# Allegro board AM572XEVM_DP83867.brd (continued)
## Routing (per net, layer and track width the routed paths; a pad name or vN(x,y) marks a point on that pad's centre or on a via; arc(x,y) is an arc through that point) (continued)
MMC1_SD_CD: length 58
  TOP w0.12: v1(63.87,9.26) 63.1,9.26 62.77,9.59 R272.2 62.77,10.99 62.57,11.19 D23.5 ; U11.W7 v2(73.79,44.81)
  INT_L3 w0.094: v2(73.79,44.81) 74.17,45.19 74.17,45.72 74.48,46.03 74.74,46.03 74.96,46.25 74.96,46.64 75.15,46.83 77.12,46.83 78.16,45.79 78.16,25.59 77.22,24.64 77.22,16.38 73.33,12.5 65.58,12.5 63.87,10.79 v1(63.87,9.26)
  BOTTOM w0.12: P12.9 v1(63.87,9.26)
MMC2_3V3: length 17.9
  TOP w0.203: U22.P3 94.61,47.36 94.61,47.62
  TOP w0.254: U22.E6 v2(92.83,43.04) 92.85,43.06 U22.F5 ; U22.J10 91.43,44.57 v2(91.44,44.58) 91.32,44.69 U22.K9
  TOP w0.381: v1(95.25,48.13) v1(94.61,48.13) 94.61,47.62
  BOTTOM w0.254: v2(91.44,44.58) 91.5,44.51 C266.1
  BOTTOM w0.381: R259.1 R254.1 R258.1 R253.1 R252.1 R257.1 R256.1 v1(97.28,37.88) 97.28,40.35 R255.1 ; R251.1 93.15,43.37 v2(92.83,43.04) 92.65,43.04 92.27,43.42 R250.1 ; v2(91.44,44.58) 90.77,44.58 C267.2 ; v1(95.25,48.13) 95.25,48.64 95.09,48.8 R249.1 v1(94.61,48.13) v1(95.25,48.13)
MMC2_CLK: length 33.8
  TOP w0.12: v2(92.33,45.57) U22.M6 ; U11.J7 v2(73.79,36.01)
  SIG_L10 w0.094: v2(92.33,45.57) 92.73,45.97 94.87,45.97 95,46.11 95,46.39 94.91,46.48 91.57,46.48 85.37,40.28 82.06,40.28 81.79,40.01 79.25,40.01 78.87,40.39 76.03,40.39 75.81,40.16 75.81,39.87 75.52,39.58 75.23,39.58 75.01,39.36 75.01,39.07 74.73,38.79 73.58,38.79 73.41,38.61 73.41,36.45 73.79,36.07 v2(73.79,36.01)
  BOTTOM w0.12: v2(92.33,45.57) 92.27,45.51 R250.2
MMC2_CMD: length 34
  TOP w0.12: v2(93.07,45.57) 93.33,45.82 U22.M5 ; U11.H6 v2(74.59,35.21)
  SIG_L10 w0.094: v2(93.07,45.57) 93.45,45.19 93.45,43.41 95.38,41.48 95.38,41.47 95.4,41.45 95.4,39.52 94.13,38.25 88.03,38.25 83.44,33.66 79.17,33.66 78.74,33.23 76.03,33.23 75.81,33.45 75.81,33.72 75.54,33.98 75.24,33.98 74.96,34.26 74.96,34.56 74.59,34.94 v2(74.59,35.21)
  BOTTOM w0.12: v2(93.07,45.57) 93.15,45.49 R251.2
MMC2_DAT0: length 33.8
  TOP w0.12: v1(94.74,39.5) 94.33,39.91 U22.A3 ; U11.J4 v2(76.19,36.01)
  SIG_L10 w0.094: v2(76.19,36.01) 76.19,35.96 76.56,35.58 78.84,35.58 79.58,36.32 83.69,36.32 87.27,39.9 87.91,39.9 88.15,40.15 88.15,40.68 88.23,40.77 88.35,40.77 88.43,40.68 88.43,39.98 88.52,39.9 88.63,39.9 88.72,39.98 88.72,40.68 88.8,40.77 88.92,40.77 89,40.68 89,39.98 89.08,39.9 89.2,39.9 89.28,39.98 89.28,40.68 89.36,40.77 89.48,40.77 89.56,40.68 89.56,39.98 89.64,39.9 89.76,39.9 89.84,39.98 89.84,40.68 89.93,40.77 90.04,40.77 90.13,40.68 90.13,39.98 90.21,39.9 90.33,39.9 90.41,39.98 90.41,40.68 90.49,40.77 90.61,40.77 90.69,40.68 90.69,39.98 90.77,39.9 90.89,39.9 90.97,39.98 90.97,40.68 91.05,40.77 91.17,40.77 91.25,40.68 91.25,39.98 91.34,39.9 91.45,39.9 91.54,39.98 91.54,40.68 91.62,40.77 91.73,40.77 91.82,40.68 91.82,40.14 92.05,39.9 94.34,39.9 v1(94.74,39.5)
  BOTTOM w0.12: R252.2 v1(94.74,39.5)
MMC2_DAT1: length 33.9
  TOP w0.12: U11.J6 v2(74.59,36.01) ; v1(93.85,39.5) 93.82,39.53 U22.A4
  SIG_L10 w0.094: v1(93.85,39.5) 94.2,39.5 94.29,39.4 94.29,38.8 93.98,38.48 93.24,38.48 93.16,38.56 93.16,38.78 93.08,38.86 92.96,38.86 92.88,38.78 92.88,38.56 92.79,38.48 92.68,38.48 92.6,38.56 92.6,38.78 92.51,38.86 92.4,38.86 92.31,38.78 92.31,38.56 92.23,38.48 92.11,38.48 92.03,38.56 92.03,38.78 91.95,38.86 91.83,38.86 91.75,38.78 91.75,38.56 91.67,38.48 91.55,38.48 91.47,38.56 91.47,38.78 91.38,38.86 91.27,38.86 91.19,38.78 91.19,38.56 91.1,38.48 90.99,38.48 90.9,38.56 90.9,38.78 90.82,38.86 90.7,38.86 90.62,38.78 90.62,38.56 90.54,38.48 90.42,38.48 90.34,38.56 90.34,38.78 90.26,38.86 90.14,38.86 90.06,38.78 90.06,38.56 89.98,38.48 89.86,38.48 89.78,38.56 89.78,38.78 89.69,38.86 89.58,38.86 89.49,38.78 89.49,38.56 89.41,38.48 89.29,38.48 89.21,38.56 89.21,38.78 89.13,38.86 89.01,38.86 88.93,38.78 88.93,38.56 88.85,38.48 88.73,38.48 88.65,38.56 88.65,38.78 88.57,38.86 88.45,38.86 88.37,38.78 88.37,38.56 88.28,38.48 88.17,38.48 88.08,38.56 88.08,38.78 88,38.86 87.88,38.86 87.8,38.78 87.8,38.56 87.72,38.48 87.6,38.48 87.52,38.56 87.52,38.78 87.44,38.86 87.32,38.86 87.24,38.78 87.24,38.56 87.16,38.48 86.93,38.48 86.84,38.39 86.84,38.25 87.12,37.97 87.12,37.72 83.69,34.29 83.31,34.29 82.91,34.69 79.65,34.69 78.94,33.98 76.08,33.98 75.81,34.25 75.81,34.68 75.66,34.83 75.23,34.83 74.96,35.09 74.96,35.63 v2(74.59,36.01)
  BOTTOM w0.12: R253.2 v1(93.85,39.5)
MMC2_DAT2: length 33.8
  TOP w0.12: v1(92.08,39.5) 92.26,39.5 U22.A5 ; U11.H4 v2(76.19,35.21)
  SIG_L10 w0.094: v2(76.19,35.21) 76.61,34.78 78.85,34.78 78.99,34.92 82.68,34.92 83.1,35.35 83.21,35.35 83.73,34.83 83.85,34.83 83.93,34.91 83.93,35.03 83.41,35.54 83.41,35.66 83.5,35.74 83.61,35.74 84.13,35.23 84.25,35.23 84.33,35.31 84.33,35.43 83.81,35.94 83.81,36.06 83.89,36.14 84.01,36.14 84.53,35.62 84.65,35.62 84.73,35.71 84.73,35.82 84.21,36.34 84.21,36.46 84.29,36.54 84.41,36.54 84.93,36.02 85.05,36.02 85.13,36.11 85.13,36.22 84.61,36.74 84.61,36.86 84.69,36.94 84.81,36.94 85.33,36.42 85.44,36.42 85.53,36.5 85.53,36.62 85.01,37.14 85.01,37.26 85.09,37.34 85.21,37.34 85.73,36.82 85.84,36.82 85.93,36.9 85.93,37.02 85.41,37.54 85.41,37.66 85.49,37.74 85.61,37.74 86.12,37.22 86.24,37.22 86.32,37.3 86.32,37.42 85.81,37.94 85.81,38.05 85.89,38.14 86.01,38.14 86.52,37.62 86.64,37.62 86.72,37.7 86.72,37.82 86.2,38.34 86.2,38.45 86.87,39.12 91.69,39.12 v1(92.08,39.5)
  BOTTOM w0.12: R254.2 v1(92.08,39.5)
MMC2_DAT3: length 34.1
  TOP w0.12: U11.H5 v2(75.39,35.21) ; U22.B2 v4(95.07,40.82)
  SIG_L10 w0.094: v4(95.07,40.82) 94.39,40.13 92.58,40.13 92.46,40.26 92.46,41.02 92.33,41.15 90.97,41.15 90.88,41.23 90.88,42.59 90.8,42.67 90.68,42.67 90.6,42.59 90.6,41.23 90.52,41.15 90.4,41.15 90.32,41.23 90.32,42.08 90.24,42.16 90.12,42.16 90.04,42.08 90.04,41.23 89.95,41.15 89.84,41.15 89.75,41.23 89.75,41.57 89.67,41.66 89.56,41.66 89.47,41.57 89.47,41.23 89.39,41.15 88.14,41.15 84.96,37.97 84.85,37.97 84.58,38.24 84.47,38.24 84.38,38.15 84.38,38.04 84.65,37.77 84.65,37.66 84.56,37.57 84.45,37.57 84.18,37.84 84.07,37.84 83.98,37.76 83.98,37.64 84.25,37.37 84.25,37.26 84.17,37.18 84.05,37.18 83.78,37.44 83.67,37.44 83.59,37.36 83.59,37.24 83.85,36.98 83.85,36.86 83.69,36.7 79.25,36.7 78.93,36.38 76.03,36.38 75.81,36.16 75.81,35.63 v2(75.39,35.21)
  BOTTOM w0.12: R255.2 95.5,40.39 v4(95.07,40.82)
MMC2_DAT4: length 35.8
  TOP w0.12: U22.B3 v4(94.58,40.82) ; U11.K7 v2(73.79,36.81)
  SIG_L10 w0.094: v2(73.79,36.81) 74.16,37.18 74.7,37.18 75.01,37.49 75.01,37.76 75.23,37.98 75.5,37.98 75.81,38.29 75.81,38.56 76.08,38.83 78.96,38.83 79.25,39.12 79.81,39.12 79.89,39.03 79.89,38.56 79.98,38.48 80.09,38.48 80.18,38.56 80.18,39.03 80.26,39.12 80.37,39.12 80.46,39.03 80.46,38.56 80.54,38.48 80.66,38.48 80.74,38.56 80.74,39.03 80.82,39.12 80.94,39.12 81.02,39.03 81.02,38.56 81.1,38.48 81.22,38.48 81.3,38.56 81.3,39.03 81.39,39.12 84.96,39.12 90.81,44.96 92.58,44.96 92.84,44.7 92.84,43.69 92.45,43.3 92.45,42.88 92.79,42.55 93.38,42.55 94.04,41.88 94.04,41.75 93.75,41.45 93.75,41.13 94.06,40.82 v4(94.58,40.82)
  BOTTOM w0.12: v4(94.58,40.82) 95.77,39.62 96.14,39.62 96.52,39.24 R256.2
MMC2_DAT5: length 35.7
  TOP w0.12: U11.M7 v2(73.79,38.41) ; U22.B4 93.83,41.06 v4(94.08,41.32)
  SIG_L10 w0.094: v4(94.08,41.32) 94.59,41.32 94.69,41.41 94.69,41.71 93.09,43.31 93.09,44.96 92.86,45.19 90.65,45.19 84.84,39.37 84.33,39.37 84.24,39.45 84.24,39.92 84.16,40.01 84.04,40.01 83.96,39.92 83.96,39.45 83.88,39.37 83.76,39.37 83.68,39.45 83.68,39.92 83.6,40.01 83.48,40.01 83.4,39.92 83.4,39.45 83.31,39.37 83.2,39.37 83.12,39.45 83.12,39.92 83.03,40.01 82.92,40.01 82.83,39.92 82.83,39.45 82.75,39.37 82.04,39.37 81.83,39.58 81.44,39.58 81.23,39.37 81.01,39.37 80.8,39.58 80.58,39.58 80.37,39.37 80.14,39.37 79.93,39.58 79.71,39.58 79.5,39.37 79.28,39.37 79.07,39.58 76.03,39.58 75.76,39.32 75.76,39.05 75.54,38.83 75.28,38.83 75.01,38.56 75.01,38.29 74.74,38.03 74.16,38.03 v2(73.79,38.41)
  BOTTOM w0.12: v4(94.08,41.32) 94.07,41.31 94.07,40.82 95.63,39.26 R257.2
MMC2_DAT6: length 34.7
  TOP w0.12: U22.B5 93.33,41.06 v4(93.58,40.82) ; U11.J5 v2(75.39,36.01)
  SIG_L10 w0.094: v4(93.58,40.82) 93.27,40.51 93.23,40.51 93.21,40.49 92.8,40.49 92.71,40.58 92.71,41.27 92.58,41.4 91.44,41.4 91.19,41.66 91.19,42.39 91.95,43.15 91.95,43.56 91.69,43.81 90.42,43.81 90.27,43.66 90.27,43.54 90.6,43.21 90.6,43.1 90.51,43.01 90.4,43.01 90.07,43.34 89.95,43.34 89.87,43.26 89.87,43.14 90.2,42.82 90.2,42.7 90.11,42.62 90,42.62 89.67,42.94 89.55,42.94 89.47,42.86 89.47,42.74 89.8,42.42 89.8,42.3 89.72,42.22 89.6,42.22 89.27,42.55 89.15,42.55 89.07,42.46 89.07,42.35 89.4,42.02 89.4,41.9 89.32,41.82 89.2,41.82 88.87,42.15 88.76,42.15 88.67,42.06 88.67,41.95 89,41.62 89,41.5 88.92,41.42 88.8,41.42 88.47,41.75 88.36,41.75 85.22,38.61 84.2,38.61 83.44,37.85 82.42,37.85 82.19,37.61 82.19,37.23 82.04,37.08 79.44,37.08 79.31,37.21 76.06,37.21 75.81,36.96 75.81,36.57 75.39,36.14 v2(75.39,36.01)
  BOTTOM w0.12: v4(93.58,40.82) 92.96,40.2 R258.2
MMC2_DAT7: length 36
  TOP w0.12: U11.K6 v2(74.59,36.81) ; U22.B6 v4(93.07,40.82)
  SIG_L10 w0.094: v2(74.59,36.81) 74.85,36.81 75.23,37.18 75.56,37.18 75.81,37.43 75.81,37.76 76.03,37.98 79,37.98 79.23,38.21 79.88,38.21 79.96,38.12 79.96,37.55 80.04,37.47 80.16,37.47 80.24,37.55 80.24,38.12 80.32,38.21 80.44,38.21 80.52,38.12 80.52,37.55 80.61,37.47 80.72,37.47 80.81,37.55 80.81,38.12 80.89,38.21 81.01,38.21 81.09,38.12 81.09,37.55 81.17,37.47 81.29,37.47 81.37,37.55 81.37,38.12 81.45,38.21 82.22,38.21 82.3,38.29 82.3,38.78 82.39,38.86 82.5,38.86 82.59,38.78 82.59,38.29 82.67,38.21 82.78,38.21 82.87,38.29 82.87,38.78 82.95,38.86 83.07,38.86 83.15,38.78 83.15,38.29 83.23,38.21 83.35,38.21 83.43,38.29 83.43,38.78 83.51,38.86 85.09,38.86 90.3,44.07 91.95,44.07 92.2,43.81 92.2,42.98 91.45,42.22 91.45,41.91 91.67,41.69 92.81,41.69 93.07,41.42 v4(93.07,40.82)
  BOTTOM w0.12: v4(93.07,40.82) 92.39,40.13 91.82,40.13 91.19,39.5 R259.2
MMC3_CLK: length 93.2
  TOP w0.12: U11.AD4 v2(76.19,48.81)
  SIG_L5 w0.094: v2(76.19,48.81) 76.2,48.82 76.2,49.78 75.03,50.95 75.03,52.09 70.61,56.52 57.63,56.52 47.22,66.93 35.05,66.93 33.02,64.9 30.35,64.9 26.92,61.47 26.92,48.64 24.26,45.97 24.26,40.13 21.59,37.47 21.08,37.47 20.85,37.7 20.85,38.11 20.6,38.35 19.34,38.35 v1(18.92,37.94)
  BOTTOM w0.12: P17.34 18.12,37.14 v1(18.92,37.94)
MMC3_CMD: length 92.3
  TOP w0.12: U11.AC4 v2(76.19,48.01)
  SIG_L5 w0.094: v1(20.45,37.94) 20.45,37.47 20.82,37.1 21.6,37.1 24.51,40.01 24.51,45.85 27.18,48.51 27.18,61.21 30.61,64.64 33.15,64.64 35.18,66.67 47.09,66.67 57.51,56.26 70.48,56.26 74.17,52.58 74.17,50.93 75.06,50.04 75.56,50.04 75.81,49.79 75.81,48.38 v2(76.19,48.01)
  BOTTOM w0.12: P17.4 21.25,37.14 v1(20.45,37.94)
MMC3_DAT0: length 90.5
  TOP w0.12: U11.AC7 v2(73.79,48.01)
  SIG_L5 w0.094: v2(73.79,48.01) 73.41,47.62 72.79,47.62 72.56,47.85 72.56,48.21 72.26,48.51 72.26,49.4 71.63,50.04 71.63,52.7 70.36,53.98 55.63,53.98 53.72,55.88 53.72,57.76 46.33,65.15 35.94,65.15 32.51,61.72 32.51,46.35 30.23,44.07 30.23,38.61 29.21,37.59 29.21,36.96 26.99,34.74 v1(21.34,34.74)
  BOTTOM w0.12: P17.7 v1(21.34,34.74)
MMC3_DAT1: length 91.4
  TOP w0.12: U11.AC6 v2(74.59,48.01)
  SIG_L5 w0.094: v2(74.59,48.01) 74.42,48.01 74,48.43 73.63,48.43 73.41,48.65 73.41,49.02 72.11,50.32 72.11,52.99 69.85,55.24 57,55.24 46.58,65.66 35.69,65.66 32,61.98 32,54.48 31.37,53.85 31.37,52.45 31.75,52.07 31.75,46.35 28.96,43.56 28.96,41.66 26.67,39.37 25.78,39.37 21.84,35.43 19.83,35.43 v1(18.92,36.34)
  BOTTOM w0.12: P17.36 18.12,35.54 v1(18.92,36.34)
MMC3_DAT2: length 90.8
  TOP w0.12: U11.AC9 v2(72.19,48.01)
  SIG_L5 w0.094: v1(20.45,34.74) 20.9,34.29 26.92,34.29 29.46,36.83 29.46,37.47 30.48,38.48 30.48,43.94 32.77,46.23 32.77,61.59 36.07,64.9 46.2,64.9 53.34,57.76 53.34,55.88 55.5,53.72 70.23,53.72 71.37,52.58 71.37,49.91 72.01,49.28 72.01,48.18 v2(72.19,48.01)
  BOTTOM w0.12: v1(20.45,34.74) 20.45,34.74 21.25,33.94 P17.8
MMC3_DAT3: length 96.5
  TOP w0.12: U11.AC3 v2(76.99,48.01)
  SIG_L5 w0.094: v2(76.99,48.01) 76.99,49.89 76.58,50.29 76.58,52.2 75.82,52.96 74.93,52.96 70.1,57.78 57.12,57.78 47.22,67.69 45.52,67.69 44.5,68.71 32.13,68.71 28.07,64.64 27.18,64.64 26.42,63.88 26.42,50.8 23.75,48.13 23.75,40.89 21.59,38.73 18.82,38.73 v1(18.03,37.94)
  BOTTOM w0.12: P17.33 v1(18.03,37.94)
MMC3_DAT4: length 90.7
  TOP w0.12: U11.AC8 v2(72.99,48.01)
  SIG_L5 w0.094: v1(18.03,34.74) 18.47,35.18 21.97,35.18 25.91,39.12 26.8,39.12 29.21,41.53 29.21,43.43 32,46.23 32,52.32 31.6,52.73 31.6,53.7 32.26,54.36 32.26,61.85 35.81,65.41 46.46,65.41 54.1,57.76 54.1,55.88 55.75,54.23 70.48,54.23 71.88,52.83 71.88,50.16 72.52,49.53 72.52,48.64 72.99,48.17 v2(72.99,48.01)
  BOTTOM w0.12: P17.37 v1(18.03,34.74)
MMC3_DAT5: length 90.8
  TOP w0.12: U11.AD6 v2(74.59,48.81)
  SIG_L5 w0.094: v2(74.59,48.81) 74.59,49.11 74.23,49.46 74.23,49.72 73.91,50.04 73.53,50.04 72.55,51.02 72.55,53.31 70.1,55.75 57.25,55.75 46.84,66.17 35.43,66.17 31.5,62.23 31.5,55.75 29.97,54.23 29.97,48.51 29.46,48.01 29.46,44.83 26.29,41.66 25.53,41.66 25.02,41.15 25.02,39.37 21.59,35.94 21.09,35.94 20.85,36.17 20.85,36.55 20.57,36.83 18.52,36.83 v1(18.03,36.34)
  BOTTOM w0.12: P17.35 v1(18.03,36.34)
MMC3_DAT6: length 93.5
  TOP w0.12: U11.AB8 v2(72.99,47.21)
  SIG_L5 w0.094: v2(72.99,47.21) 72.72,47.21 72.3,47.62 72.01,47.62 71.79,47.85 71.79,49.12 71.12,49.78 71.12,52.45 70.1,53.47 55.37,53.47 52.96,55.88 52.96,57.76 46.08,64.64 36.2,64.64 33.02,61.47 33.02,46.1 30.73,43.81 30.73,38.35 29.72,37.34 29.72,36.7 27.05,34.04 19.63,34.04 v1(18.92,34.74)
  BOTTOM w0.12: P17.38 18.12,33.94 18.92,34.74 v1(18.92,34.74)
MMC3_DAT7: length 91.9
  TOP w0.12: U11.AB5 v2(75.39,47.21)
  SIG_L5 w0.094: v2(75.39,47.21) 75.01,47.58 75.01,48.18 74.8,48.39 74.42,48.39 74.17,48.64 74.17,49.02 73.94,49.25 73.64,49.25 72.33,50.57 72.33,53.15 69.98,55.5 57.12,55.5 46.71,65.91 35.56,65.91 31.75,62.1 31.75,55.63 30.59,54.46 30.59,52.85 31.5,51.94 31.5,46.48 28.7,43.69 28.7,41.78 26.54,39.62 25.65,39.62 21.72,35.69 20.83,35.69 20.45,36.07 v1(20.45,36.34)
  BOTTOM w0.12: P17.6 21.25,35.54 v1(20.45,36.34)
Net_98: length 2.7
  BOTTOM w0.12: v1(116.71,18.74) 115.91,17.94 114.33,17.94
Net_117: length 0.6
  TOP w0.12: 67.79,48.41 v2(68.19,48.81)
Net_118: length 0.6
  TOP w0.12: 69.79,69.21 v2(70.19,68.81)
Net_173: length 0.6
  TOP w0.12: v2(40.98,41.61) 41.38,42.01
Net_174: length 0.6
  TOP w0.12: v2(40.98,52.81) 41.38,53.21
Net_175: length 0.6
  TOP w0.12: v2(39.38,52.81) 39.78,53.21
Net_176: length 0.6
  TOP w0.12: v2(39.38,41.61) 39.78,42.01
Net_177: length 0.6
  TOP w0.12: v2(40.98,60.01) 41.38,59.61
Net_178: length 0.6
  TOP w0.12: v2(40.98,48.81) 41.38,48.41
Net_179: length 0.6
  TOP w0.12: v2(39.38,48.81) 39.78,48.41
Net_232: length 0.6
  TOP w0.12: v2(63.79,69.61) 64.19,70.01
Net_1052: length 0.6
  TOP w0.12: v2(40.98,26.4) 41.38,26
Net_1053: length 0.6
  TOP w0.12: v2(40.98,19.2) 41.38,19.6
Net_1054: length 0.6
  TOP w0.12: v2(39.38,19.2) 39.78,19.6
Net_1055: length 0.6
  TOP w0.12: v2(39.38,26.4) 39.78,26
Net_1056: length 0.6
  TOP w0.12: v2(40.98,37.6) 41.38,37.2
Net_1057: length 0.6
  TOP w0.12: v2(40.98,30.4) 41.38,30.8
Net_1058: length 0.6
  TOP w0.12: v2(39.38,30.4) 39.78,30.8
Net_1059: length 0.6
  TOP w0.12: v2(39.38,37.6) 39.78,37.2
OC0: length 20.7
  TOP w0.12: U17.46 89.96,33.7 v1(89.66,33.4)
  BOTTOM w0.12: U29.10 103.71,26.49 103,25.78 100.71,25.78 99.31,27.18 99.31,27.94 99.06,28.19 99.06,30.1 98.04,31.11 95.89,31.11 94.61,32.38 90.42,32.38 89.66,33.15 v1(89.66,33.4)
OC1: length 19.1
  TOP w0.12: U17.47 89.46,35.11 v1(89.66,35.31)
  BOTTOM w0.12: v1(89.66,35.31) 90.08,34.89 90.08,33.11 90.55,32.64 94.87,32.64 95.44,32.07 99,32.07 100.58,30.48 102.62,30.48 103.71,29.39 U29.6
OC2: length 16.2
  TOP w0.12: U17.44 90.96,33.89 90.64,33.57 90.64,33.56 v1(90.49,33.41)
  BOTTOM w0.12: U30.10 103.71,31.57 102.87,30.73 100.71,30.73 99.12,32.32 95.69,32.32 95.12,32.89 90.93,32.89 90.49,33.33 v1(90.49,33.41)
OC3: length 14.7
  TOP w0.12: U17.43 91.46,33.76 91.82,33.4 v1(95,33.4)
  BOTTOM w0.12: U30.6 103.71,34.47 102.62,35.56 97.16,35.56 v1(95,33.4)
OSC0_XI: length 9.2
  TOP w0.12: U11.AE15 v2(66.59,49.61) ; C101.1 65.15,54.99 v1(64.9,54.74) 64.26,54.74 63.55,55.45 Y2.1
  GND_L9 w0.094: v2(66.59,49.61) 66.17,50.02 66.17,53.47 v1(64.9,54.74)
OSC0_XO: length 16.7
  TOP w0.12: C100.1 v1(57.66,54.74) 58.55,54.74 59.26,55.45 Y2.2 ; U11.AD15 v2(66.59,48.81)
  GND_L9 w0.094: v1(57.66,54.74) 58.17,54.23 63.5,54.23 65.41,52.32 65.41,49.4 65.63,49.18 66.21,49.18 v2(66.59,48.81)
OSC1_XI: length 10.3
  TOP w0.12: v1(66.68,54.74) 66.55,54.74 66.29,54.99 C103.1 67.54,55.41 Y3.1 ; U11.AC15 v2(66.59,48.01)
  GND_L9 w0.094: v2(66.59,48.01) 67.06,48.47 67.06,54.36 v1(66.68,54.74)
OSC1_XO: length 14.6
  TOP w0.12: v1(71.63,57.02) C102.1 70.39,56.35 Y3.3 ; U11.AC13 v2(68.99,48.01)
  GND_L9 w0.094: v2(68.99,48.01) 68.6,48.39 67.94,48.39 67.56,48.77 67.56,52.96 v1(71.63,57.02)
PCI_CONN_REFN: length 20
  TOP w0.102: U7.2 30.39,53.35 30.39,58 29.72,58.67 25.63,58.67 23.75,60.55 19,60.55 18.3,59.85 v1(18.03,59.85)
  BOTTOM w0.12: P19.58 v1(18.03,59.85)
PCI_CONN_REFP: length 19.9
  TOP w0.102: U7.3 30.03,53.35 30.03,57.86 29.57,58.32 25.48,58.32 23.6,60.2 19.15,60.2 18.92,59.97 v1(18.92,59.85)
  BOTTOM w0.12: v1(18.92,59.85) 18.92,59.55 18.8,59.43 17.87,59.43 17.78,59.35 17.78,59.18 17.65,59.05 P19.59
PCIE_TXN0: length 3.1
  TOP w0.12: U11.AG14 v3(68.19,51.21)
  BOTTOM w0.102: v3(68.19,51.21) 67.77,51.62 67.77,52.24 67.44,52.58 67.34,52.58 C423.1
PCIE_TXN1: length 3.4
  TOP w0.12: U11.AG12 v3(69.79,51.21)
  BOTTOM w0.102: v3(69.79,51.21) 69.4,51.6 69.4,53.83 C425.1
PCIE_TXP0: length 1.9
  TOP w0.12: U11.AH14 v3(68.19,52.01)
  BOTTOM w0.102: C422.1 67.69,52.83 68.19,52.34 v3(68.19,52.01)
PCIE_TXP1: length 2.7
  TOP w0.12: U11.AH12 v3(69.79,52.01)
  BOTTOM w0.102: v3(69.79,52.01) 69.75,52.04 69.75,52.99 70.23,53.47 C424.1
PMIC_BOOT0: length 4.1
  TOP w0.12: U5.L3 v2(62.99,76.01)
  BOTTOM w0.12: v2(62.99,76.01) 62.58,76.42 60.71,76.42 R20.1 R21.1
PMIC_BOOT1: length 5.2
  TOP w0.12: U5.K7 v2(63.79,72.81)
  BOTTOM w0.12: R22.1 R214.1 61.21,72.39 62.02,73.2 63.4,73.2 v2(63.79,72.81)
PMIC_GPIO_0: length 2.3
  TOP w0.12: v2(70.99,68.81) U5.B12
  BOTTOM w0.12: R421.1 72.14,68.33 71.65,68.81 v2(70.99,68.81)
PMIC_GPIO_3: length 5.7
  TOP w0.12: U5.H9 v2(65.39,70.41)
  BOTTOM w0.12: R26.1 67.06,69.47 66.52,70 65.79,70 v2(65.39,70.41)
PMIC_GPIO_5: length 5.9
  TOP w0.12: v2(70.19,69.61) U5.C10
  BOTTOM w0.12: R27.1 74.84,69.69 74.68,69.85 72.14,69.85 71.99,70 70.58,70 v2(70.19,69.61)
PMIC_INT: length 49
  TOP w0.12: U11.AD17 v2(64.99,48.81) ; U5.K1 v2(63.79,77.61)
  INT_L3 w0.094: v2(63.79,77.61) 63.39,77.22 62.74,77.22 62.56,77.04 62.56,67.85 61.85,67.14 61.85,60.33 67.09,55.08 67.09,49.56 66.71,49.18 65.44,49.18 65.06,48.81 v2(64.99,48.81)
  BOTTOM w0.12: R48.2 57.12,53.12 58.17,52.07 58.17,51.31 58.67,50.8 59.22,50.8 59.22,50.81 59.56,50.81 59.79,50.58 59.79,50.24 60.02,50.01 61.95,50.01 62.19,49.77 62.19,47.84 62.42,47.61 65.15,47.61 65.39,47.84 65.39,48.17 64.99,48.57 v2(64.99,48.81)
PMIC_OFF: length 35.6
  TOP w0.12: U11.Y11 v2(70.59,45.61)
  INT_L3 w0.094: v2(70.59,45.61) 70.59,45.62 70.99,46.03 70.99,63.75 72.64,65.41 72.64,75.95 71.84,76.76 71.84,76.8 71.81,76.82 v2(71.81,76.85)
  BOTTOM w0.12: R322.1 70.87,78.27 R45.2 71.42,78.21 71.42,77.23 v2(71.81,76.85)
PMIC_POWERGOOD: length 14.9
  TOP w0.12: U5.J7 v2(64.59,72.81)
  SIG_L10 w0.094: TP5.1 59.36,80.85 59.82,80.39 59.82,74.5 61.14,73.18 64.22,73.18 v2(64.59,72.81)
PMIC_POWERHOLD: length 16
  TOP w0.12: U5.G9 v2(66.19,70.41)
  BOTTOM w0.12: J5.1 74.17,64.01 71.88,64.01 71.59,64.3 69.82,64.3 69.6,64.52 69.6,66.27 69.48,66.39 R23.2 R28.2 68.07,66.93 68.2,67.05 68.2,69.75 67.95,70 67.16,70 66.75,70.41 v2(66.19,70.41)
PMIC_RESET_IN: length 16.4
  TOP w0.12: U13.1 53.01,68.63 53.24,68.86 v1(53.24,69.49) ; U5.K9 63.8,70.43 v2(63.8,70.41)
  BOTTOM w0.12: v2(63.8,70.41) 63.4,70.82 63.4,71.61 63.13,71.88 58.93,71.88 58.55,71.5 58.55,70.36 58.17,69.98 56.11,69.98 55.3,69.16 54.15,69.16 53.82,69.49 v1(53.24,69.49) R56.2
PMIC_RESET_OUT: length 20.7
  TOP w0.12: v2(66.99,73.61) U5.G6
  BOTTOM w0.12: v2(66.99,73.61) 66.42,73.04 66.42,71.88 66.68,71.62 67.95,71.62 68.2,71.38 68.2,70.99 68.37,70.82 69.55,70.82 69.78,70.59 69.78,67.82 70,67.6 71.21,67.6 71.38,67.43 71.38,67.05 71.88,66.55 71.88,64.52 72.1,64.3 75.91,64.3 76.33,63.88 76.33,62.74 76.52,62.55 U9.1
PMIC_SCE: length 5.6
  TOP w0.12: U5.M3 v2(62.19,76.01)
  INT_L3 w0.094: v2(62.19,76.01) 61.76,76.43 61.76,79.04 v1(62.61,79.88)
  BOTTOM w0.12: R19.1 v1(62.61,79.88)
PMIC_SDO: length 14.4
  TOP w0.12: U5.H8 v2(65.39,71.21)
  INT_L3 w0.094: v1(61.59,79.88) 62.1,80.39 64.9,80.39 65.76,79.52 65.76,72.49 65.39,72.12 v2(65.39,71.21)
  BOTTOM w0.12: R18.1 v1(61.59,79.88)
PMIC_VBUS_DET: length 92.4
  TOP w0.12: U5.C13 v2(70.19,67.21)
  INT_L3 w0.094: v1(78.23,20.83) 79.76,22.35 79.76,29.84 80.65,30.73 81.28,30.73 81.79,31.24 81.79,33.53 81.28,34.04 81.28,39.88 81.79,40.39 81.79,43.94 80.52,45.21 80.52,48.51 80.01,49.02 80.01,52.2 79.5,52.7 79.5,57.91 80.01,58.42 80.01,60.71 79.5,61.21 79.5,61.85 80.26,62.61 80.26,64.52 v1(78.61,66.17)
  SIG_L10 w0.094: v1(97.79,9.65) 97.54,9.4 79.12,9.4 77.6,10.92 77.6,20.19 v1(78.23,20.83) ; v2(70.19,67.21) 72.24,65.15 77.6,65.15 v1(78.61,66.17)
  BOTTOM w0.12: v1(97.79,9.65) 97.54,9.65 97.28,9.4 R414.1
PMIC_XTAL_IN: length 11.8
  TOP w0.12: U5.A3 v2(71.79,76.01)
  BOTTOM w0.12: C452.1 75.85,80.48 75.31,81.02 75.31,81.18 74.55,81.94 73.05,81.94 72.77,81.66 72.77,81.15 71.82,80.2 71.82,77.64 72.21,77.24 72.21,76.43 v2(71.79,76.01)
PMIC_XTAL_OUT: length 4.2
  TOP w0.12: v2(72.46,77.7) 72.46,76.8 72.07,76.41 U5.A2
  BOTTOM w0.12: Y9.1 72.98,78.78 72.48,78.29 C453.1 v2(72.46,77.7)
POR_CT: length 2.6
  TOP w0.12: U12.4 59.65,7.87 v1(58.67,7.87)
  BOTTOM w0.12: v1(58.67,7.87) 58.55,8 57.15,8
PORZ: length 53.7
  TOP w0.12: U11.AB17 v2(64.99,47.21) ; U11.F22 v2(60.99,33.61)
  SIG_L8 w0.094: v2(64.99,47.21) 64.86,47.21 64.48,46.83 62.45,46.83 62.18,46.56 62.18,34.24 61.98,34.04 61.42,34.04 v2(60.99,33.61)
  SIG_L10 w0.094: v1(78.12,61.47) 77.74,61.85 73.91,61.85 67.18,55.12 67.18,48.01 66.8,47.62 65.41,47.62 v2(64.99,47.21)
  BOTTOM w0.12: C95.2 U11.AB17 v2(64.99,47.21) 65.1,47.21 65.5,47.61 65.95,47.61 66.19,47.84 66.19,48.17 66.42,48.41 66.75,48.41 67.31,48.96 R57.1 ; R39.1 61.21,29.08 61.39,29.26 61.39,31.37 61.62,31.61 61.96,31.61 62.19,31.83 62.19,33.77 61.95,34.01 61.3,34.01 C96.2 61.3,33.92 v2(60.99,33.61) ; U9.4 v1(78.12,61.47)
PR1_UART0_CTSN: length 43.5
  TOP w0.12: U11.G1 v2(78.59,34.41)
  SIG_L5 w0.094: v2(78.59,34.41) 79.24,34.41 80.26,35.43 88.77,35.43 89.28,34.92 103.12,34.92 105.54,32.51 116.46,32.51 116.71,32.77 v1(116.71,33.14)
  BOTTOM w0.12: v1(116.71,33.14) 115.91,32.34 P18.40
PR1_UART0_RTSN: length 48.7
  TOP w0.12: U11.G6 v2(74.59,34.41)
  SIG_L5 w0.094: v2(74.59,34.41) 74.59,34.67 75.01,35.09 75.01,35.36 75.28,35.63 75.54,35.63 75.81,35.89 75.81,36.16 76.08,36.43 76.34,36.43 77.41,37.49 77.41,37.76 77.68,38.03 77.94,38.03 78.21,38.29 78.21,38.56 78.48,38.83 78.96,38.83 79.25,39.12 84.71,39.12 84.96,38.86 98.55,38.86 99.57,39.88 110.68,39.88 v1(115.82,34.74)
  BOTTOM w0.12: P18.37 v1(115.82,34.74)
PR1_UART0_RXD: length 42.8
  TOP w0.12: U11.F2 v2(77.79,33.61)
  SIG_L5 w0.094: v2(77.79,33.61) 78.16,33.23 78.89,33.23 80.58,34.92 88.27,34.92 89.28,33.91 99.06,33.91 99.57,34.42 102.87,34.42 105.28,32 115.35,32 v1(115.82,31.54)
  BOTTOM w0.12: P18.41 v1(115.82,31.54)
PR1_UART0_TXD: length 47.2
  TOP w0.12: U11.F3 v2(76.99,33.61)
  SIG_L5 w0.094: v1(118.24,33.14) 117.36,32.26 105.41,32.26 103,34.67 99.38,34.67 98.87,34.16 96.9,34.16 96.39,34.67 89.03,34.67 88.52,35.18 80.39,35.18 79.24,34.03 77.41,34.03 v2(76.99,33.61)
  BOTTOM w0.12: v1(118.24,33.14) 119.04,32.34 P18.10
PS_3V3: length 115.5
  TOP w0.254: U5.N3 v2(61.39,75.21) U5.N4 v2(62.19,75.21) ; U5.N3 v2(62.19,75.21) ; U5.N3 v2(61.39,76.01) ; U5.H12 66.19,68.01 v2(66.19,68.01) ; U5.H12 v2(66.19,68.81) ; U5.H12 v2(65.39,68.01) U5.H13 ; U5.H12 v2(65.39,68.81) U5.H11 65.79,69.21 v2(66.19,68.81) ; U5.N9 v2(62.19,71.21) ; U5.N9 v2(61.39,71.21) U5.N8 v2(62.19,71.21) ; U5.N9 61.79,70.81 v2(62.19,70.41) U5.M9 v2(62.19,71.21) ; U5.N9 v2(61.39,70.41) ; v2(62.19,71.21) U5.M8 ; v2(69.39,67.21) U5.D13 68.99,67.61 v2(69.39,68.01) U5.D12 68.99,68.41 v2(69.39,68.81) U5.D11 ; U5.L12 v2(62.99,68.01) U5.L13 v2(62.99,67.21) ; U5.H13 v2(66.19,67.21) U5.G13 v2(66.19,68.01) ; U5.H13 v2(66.19,68.01) ; U5.H13 v2(65.39,67.21) ; v2(66.19,68.01) U5.G12 v2(66.19,68.81) ; v2(68.59,77.61) U5.E1 v2(68.59,76.81) U5.E2 68.19,76.41 68.59,76.01 U5.E3 ; U5.F3 v2(67.79,76.01) 67.39,76.41 U5.F2 v2(67.79,76.81) U5.F1 v2(67.79,77.61) ; 43.93,71.24 v1(43.94,71.25) ; v2(70.19,75.21) U5.C4 v2(70.19,74.41) U5.C5 ; U5.J3 v2(64.59,76.01) U5.J2 v2(64.59,76.81) U5.J1 v2(64.59,77.61) ; v2(66.19,68.81) U5.G11 ; v2(62.19,75.21) U5.M4 ; v2(61.39,73.61) U5.N6 v2(62.19,73.61) U5.M6 ; v2(70.19,72.01) U5.C7
  TOP w0.381: v1(74.17,68.33) 74.07,68.23 R29.1 ; U13.5 U13.6 52.9,65.56 v1(53.14,65.56) ; R335.1 v1(28.58,16.38) ; 75.06,66.93 C442.1 75.56,66.93 75.56,66.29 v1(75.69,66.17) v1(74.93,66.17) 75.06,66.29 75.06,66.93
  TOP w1.016: P3.1 R7.2
  SIG_L5 w0.381: v1(32.89,76.33) 32.89,87 29.72,90.17 v1(29.72,104.27)
  PWR_L6 w0.381: 56.21,82.22 P3.1 ; P3.1 56.21,80.34 ; P3.1 58.09,82.22 ; P3.1 58.09,80.34
  SIG_L10 w0.381: v1(75.69,66.17) v1(74.93,66.17)
  BOTTOM w0.254: C26.2 72.55,75.6 72.9,75.95 73.33,75.95 73.65,76.27 73.65,76.43
  BOTTOM w0.381: v2(68.59,76.81) 68.59,76.01 v2(67.79,76.01) v2(67.79,76.81) ; v2(68.59,76.81) v2(67.79,76.81) ; v2(68.59,76.81) v2(68.59,77.61) ; C48.1 61.22,71.37 v2(61.39,71.21) ; v2(61.39,70.41) v2(61.39,71.21) ; v2(61.39,70.41) v2(62.19,70.41) v2(62.19,71.21) v2(61.39,71.21) ; v2(61.39,70.41) 60.72,70.41 C46.1 ; R407.1 v1(29.72,104.27) ; v1(53.14,65.56) C111.1 R58.1 ; v1(73.28,77.34) 73.65,76.97 R30.1 73.65,76.43 73.7,76.38 74.15,76.38 74.84,75.69 C27.2 ; R10.1 43.94,70.65 v1(43.94,71.25) ; v2(67.79,77.61) 67.79,78.17 C39.1 ; v2(67.79,77.61) v2(67.79,76.81) ; v2(67.79,77.61) v2(68.59,77.61) ; C23.1 v1(59.05,67.56) ; C33.1 70.1,66.49 v2(69.39,67.21) v2(69.39,68.01) v2(69.39,68.81) ; C43.1 60.67,74.32 v2(61.39,73.61) v2(62.19,73.61) ; C35.1 66.04,67.06 v2(66.19,67.21) ; v2(66.19,68.01) v2(65.39,68.01) ; v2(66.19,68.01) v2(66.19,67.21) ; v2(66.19,68.01) v2(66.19,68.81) v2(65.39,68.81) v2(65.39,68.01) ; v2(65.39,68.01) v2(65.39,67.21) ; v2(65.39,67.21) v2(66.19,67.21) ; v2(65.39,67.21) 65.02,66.85 C37.1 ; v1(32.89,76.33) 32.35,76.87 R13.1 ; C41.1 64.64,77.67 v2(64.59,77.61) v2(64.59,76.81) v2(64.59,76.01) ; v2(68.59,77.61) 68.59,78.14 C45.1
  vias: v1(44.7,71.25) v2(71.79,67.21)
PS_3V3_COMP: length 6.8
  TOP w0.381: C11.1 36.61,76.83 36.34,77.1 36.34,78.34 36.07,78.61 C12.1 U3.6
PS_3V3_EN: length 4.2
  TOP w0.381: v1(25.02,78.61) U3.3
  BOTTOM w0.381: v1(25.02,78.61) R11.1 25.69,79.03 25.91,79.25 26.42,79.25 26.64,79.47 R9.2
PS_3V3_SNS: length 2.7
  TOP w0.381: U3.5 v1(30.73,77.34)
  BOTTOM w0.381: R14.2 v1(30.73,77.34) R13.2
PS_3V3_SS: length 2.4
  TOP w0.381: U3.4 v1(25.02,77.34)
  BOTTOM w0.254: v1(25.02,77.34) C13.1
PS_3V3_TAP: length 2.7
  TOP w0.381: 47.93,82.22 P2.1 46.05,82.22
  vias: v1(36,87.19) v1(36.76,87.19)
PUSB_RXN0: length 41.2
  TOP w0.127: v3(85.78,32.38) 85.41,32.02 85.41,30.45 C242.1 ; U11.AF12 v3(69.79,50.41)
  BOTTOM w0.127: v3(69.79,50.41) 70.19,50.81 70.75,50.81 70.99,51.05 70.99,52.45 73.13,54.58 79.22,54.58 80.34,53.47 82.04,53.47 84.45,51.05 84.45,48.64 85.76,47.33 85.76,32.42 85.78,32.4 v3(85.78,32.38)
PUSB_RXP0: length 41.1
  TOP w0.127: v3(85.78,31.72) 85.76,31.71 85.76,30.86 C241.1 ; U11.AE12 v3(69.79,49.61)
  BOTTOM w0.114: 69.91,50.01 70.82,50.01
  BOTTOM w0.127: 70.82,50.01 71.01,50.19 71.01,50.56 71.35,50.9 71.35,52.3 73.27,54.23 79.07,54.23 80.19,53.11 81.89,53.11 84.1,50.9 84.1,48.49 85.41,47.19 85.41,34.16 85.3,34.05 85.18,34.05 85.06,33.94 85.06,33.78 85.18,33.67 85.3,33.67 85.41,33.56 85.41,33.4 85.3,33.29 85.18,33.29 85.06,33.18 85.06,33.02 85.18,32.91 85.3,32.91 85.41,32.8 85.41,32.12 v3(85.78,31.72) ; v3(69.79,49.61) 69.79,49.88 69.91,50.01
PUSB_TXN0: length 39.7
  TOP w0.127: C244.1 85.68,28.65 85.15,28.65 84.42,29.38 84.21,29.58 84.21,31.74 v3(84.2,31.75) ; U11.AC11 v3(70.59,48.01)
  BOTTOM w0.127: v3(84.2,31.75) 83.44,32.51 83.44,46.48 82.3,47.62 82.3,50.17 81.38,51.08 80.37,51.08 78.99,52.45 73.95,52.45 73.15,52.45 72.52,51.82 72.52,50.51 70.98,48.97 70.98,48.4 v3(70.59,48.01)
PUSB_TXP0: length 39.7
  TOP w0.127: U11.AD11 v3(70.59,48.81) ; C239.1 85.68,29.01 85.29,29.01 84.57,29.73 84.57,32.02 v3(84.2,32.38)
  BOTTOM w0.127: v3(70.59,48.81) 70.59,49.07 70.99,49.48 70.99,49.49 72.16,50.65 72.16,51.96 73,52.81 74.1,52.81 79.14,52.81 80.51,51.44 81.53,51.44 82.65,50.31 82.65,47.77 83.79,46.63 83.79,33.52 83.91,33.41 83.96,33.41 84.07,33.29 84.07,33.14 83.96,33.02 83.91,33.02 83.79,32.91 83.79,32.66 84.07,32.38 84.2,32.38 v3(84.2,32.38)
PWRON: length 153.3
  TOP w0.12: U5.G8 v2(66.19,71.21)
  INT_L3 w0.094: v1(101.09,56.46) 108.28,56.46 110.62,54.13 110.62,42.04 115.44,37.21 118.26,37.21 v1(119.13,36.34) ; v1(25.02,82.93) 26.67,84.58 26.67,88.9 26.96,89.19 S1.2 ; v2(66.19,71.21) 65.79,70.81 65.79,65.02 v1(66.04,64.77)
  SIG_L10 w0.094: v2(66.19,71.21) 64.98,72.42 61.16,72.42 58.93,74.65 54.38,74.65 49.02,80.01 45.47,80.01 44.96,79.5 30.99,79.5 30.61,79.88 28.07,79.88 v1(25.02,82.93) ; v1(66.04,64.77) 66.55,64.26 82.09,64.26 89.89,56.46 v1(101.09,56.46)
  BOTTOM w0.12: R407.2 C478.1 27.53,105.88 S1.2 ; P18.5 v1(119.13,36.34)
R_3V3LED: length 2.7
  TOP w0.12: R8.2 43.53,64.64 D3.2 41.91,64.64 v1(41.4,64.14)
R_12VLED: length 1.3
  TOP w0.12: D41.2 R240.2
R_EMAC[0]_TXC: length 18.8
  TOP w0.12: U14.29 90.5,62.49 89,60.99 89,58.32 87.83,57.15 87.02,57.15 86.55,56.68 86.4,56.68 86.21,56.88 86.06,56.88 85.96,56.77 85.96,56.62 86.15,56.43 86.15,56.28 86.04,56.17 85.89,56.17 85.7,56.37 85.55,56.37 85.45,56.26 85.45,56.11 85.64,55.92 85.64,55.77 85.54,55.66 85.39,55.66 85.19,55.86 85.04,55.86 84.94,55.75 84.94,55.6 85.13,55.41 85.13,55.26 85.03,55.16 84.88,55.16 84.68,55.35 84.53,55.35 84.43,55.24 84.43,55.1 84.62,54.9 84.62,54.75 84.52,54.65 84.37,54.65 84.18,54.84 84.03,54.84 83.92,54.74 83.92,54.59 84.11,54.39 84.11,54.24 84.01,54.14 83.86,54.14 83.67,54.33 83.52,54.33 83.41,54.23 83.41,54.08 83.61,53.88 83.61,53.74 83.31,53.44 R85.2
R_EMAC[0]_TXCTL: length 17.7
  TOP w0.12: R84.2 84.07,53.31 87.27,56.52 87.83,56.52 89.53,58.22 v1(89.53,59.36) ; v1(94.77,63.09) 94.75,63.11 U14.37
  INT_L3 w0.094: v1(94.77,63.09) 94.77,62.51 91.62,59.36 v1(89.53,59.36)
R_EMAC[0]_TXD0: length 22.1
  TOP w0.12: R86.2 82.55,52.53 82.44,52.63 82.3,52.63 82.19,52.74 82.19,52.99 82.3,53.09 82.44,53.09 82.55,53.2 82.55,54.23 82.84,54.52 82.84,54.67 82.6,54.91 82.6,55.06 82.7,55.17 82.85,55.17 83.1,54.92 83.25,54.92 83.35,55.03 83.35,55.18 83.11,55.42 83.11,55.57 83.21,55.68 83.36,55.68 83.61,55.43 83.75,55.43 83.86,55.54 83.86,55.69 83.61,55.93 83.61,56.08 83.72,56.19 83.87,56.19 84.11,55.94 84.26,55.94 84.37,56.05 84.37,56.2 84.12,56.44 84.12,56.59 84.23,56.7 84.38,56.7 84.62,56.45 84.77,56.45 84.88,56.56 84.88,56.7 84.63,56.95 84.63,57.1 84.74,57.2 84.89,57.2 85.13,56.96 85.28,56.96 85.39,57.06 85.39,57.21 85.14,57.46 85.14,57.61 85.25,57.71 85.39,57.71 85.64,57.47 85.79,57.47 86.06,57.73 87.83,57.73 88.44,58.34 88.44,58.65 88.34,58.76 88.19,58.76 88.09,58.86 88.09,59.01 88.19,59.12 88.34,59.12 88.44,59.22 88.44,59.37 88.34,59.48 88.19,59.48 88.09,59.58 88.09,59.73 88.19,59.84 88.34,59.84 88.44,59.94 88.44,60.09 88.34,60.2 88.19,60.2 88.09,60.3 88.09,60.45 88.19,60.56 88.34,60.56 88.44,60.66 88.44,60.91 90,62.47 U14.28
R_EMAC[0]_TXD1: length 24.4
  TOP w0.12: R87.2 81.79,53.02 81.68,53.13 81.11,53.13 81,53.23 81,53.48 81.11,53.59 81.68,53.59 81.79,53.69 81.79,54.89 82.25,55.35 82.25,55.5 82.03,55.72 82.03,55.87 82.13,55.97 82.28,55.97 82.5,55.75 82.65,55.75 82.76,55.86 82.76,56.01 82.54,56.23 82.54,56.37 82.64,56.48 82.79,56.48 83.01,56.26 83.16,56.26 83.26,56.37 83.26,56.52 83.05,56.73 83.05,56.88 83.15,56.99 83.3,56.99 83.52,56.77 83.67,56.77 83.77,56.87 83.77,57.02 83.55,57.24 83.55,57.39 83.66,57.5 83.81,57.5 84.03,57.28 84.18,57.28 84.28,57.38 84.28,57.53 84.06,57.75 84.06,57.9 84.17,58.01 84.32,58.01 84.54,57.79 84.69,57.79 84.81,57.91 84.81,58.09 84.68,58.22 84.68,58.42 85.14,58.88 85.64,58.88 85.75,58.77 85.75,58.37 85.85,58.27 86.21,58.27 86.31,58.37 86.31,58.77 86.42,58.88 86.74,58.88 87.2,58.42 87.58,58.42 87.73,58.57 87.73,58.85 87.61,58.97 87.46,58.97 87.35,59.08 87.35,59.23 87.46,59.33 87.63,59.33 87.73,59.44 87.73,59.59 87.63,59.69 87.46,59.69 87.35,59.8 87.35,59.95 87.46,60.05 87.63,60.05 87.73,60.16 87.73,60.31 87.63,60.41 87.46,60.41 87.35,60.52 87.35,60.67 87.46,60.77 87.63,60.77 87.73,60.88 87.73,61.14 87.96,61.37 88.39,61.37 89.5,62.47 U14.27
R_EMAC[0]_TXD2: length 25
  TOP w0.12: U14.26 89,62.46 88.27,61.72 87.27,61.72 86.59,61.04 86.59,59.87 86.03,59.31 84.84,59.31 84.42,58.89 84.27,58.89 84.09,59.07 83.94,59.07 83.84,58.97 83.84,58.82 84.02,58.64 84.02,58.49 83.91,58.38 83.76,58.38 83.58,58.57 83.43,58.57 83.33,58.46 83.33,58.31 83.51,58.13 83.51,57.98 83.4,57.88 83.25,57.88 83.07,58.06 82.92,58.06 82.82,57.95 82.82,57.8 83,57.62 83,57.47 82.89,57.37 82.75,57.37 82.56,57.55 82.42,57.55 82.31,57.44 82.31,57.29 82.49,57.11 82.49,56.96 82.19,56.67 80.11,56.67 79.65,56.21 79.65,55.83 79.76,55.72 80.34,55.72 80.44,55.62 80.44,55.47 80.34,55.37 79.76,55.37 79.65,55.26 79.65,55.11 79.76,55.01 80.34,55.01 80.44,54.9 80.44,54.75 80.34,54.65 79.76,54.65 79.65,54.54 79.65,54.39 79.76,54.29 80.34,54.29 80.44,54.18 80.44,54.03 80.34,53.93 79.76,53.93 79.65,53.82 79.65,53.67 79.76,53.57 80.34,53.57 80.44,53.46 80.44,53.01 81.03,52.43 R88.2
R_EMAC[0]_TXD3: length 26.1
  TOP w0.12: U14.25 88.5,62.49 88.09,62.08 86.51,62.08 85.88,61.44 85.88,60.45 85.19,59.77 83.79,59.77 83.29,59.26 83.14,59.26 82.71,59.68 82.56,59.68 82.46,59.57 82.46,59.43 82.88,59 82.88,58.85 82.78,58.75 82.63,58.75 82.21,59.17 82.06,59.17 81.95,59.07 81.95,58.92 82.37,58.49 82.37,58.34 81.86,57.84 79.83,57.84 79.16,57.16 79.16,56.04 79.05,55.93 78.29,55.93 78.18,55.83 78.18,55.68 78.29,55.57 79.05,55.57 79.16,55.47 79.16,55.32 79.05,55.21 78.29,55.21 78.18,55.11 78.18,54.96 78.29,54.85 79.05,54.85 79.16,54.75 79.16,54.6 79.05,54.49 78.29,54.49 78.18,54.39 78.18,54.24 78.29,54.13 79.05,54.13 79.16,54.03 79.16,53.14 R89.2
R_EMAC[1]_TXC: length 41.5
  TOP w0.12: U15.29 104.25,62.75 102.82,61.32 102.82,60.84 102.71,60.73 102.42,60.73 102.31,60.63 102.31,60.48 102.42,60.37 102.71,60.37 102.82,60.27 102.82,59.69 102.46,59.33 102.31,59.33 102.14,59.49 101.99,59.49 101.88,59.39 101.88,59.24 102.05,59.07 102.05,58.92 101.95,58.82 101.8,58.82 101.63,58.99 101.48,58.99 101.38,58.88 101.38,58.73 101.54,58.56 101.54,58.41 101.44,58.31 101.29,58.31 101.12,58.48 100.97,58.48 100.87,58.37 100.87,58.22 101.03,58.05 101.03,57.91 100.93,57.8 100.78,57.8 100.61,57.97 100.46,57.97 100.36,57.86 100.36,57.71 100.53,57.55 100.53,57.4 100.42,57.29 100.27,57.29 100.1,57.46 99.95,57.46 99.85,57.35 99.85,57.21 100.02,57.04 100.02,56.89 99.75,56.62 97.16,56.62 92.41,51.87 91.64,51.87 87.55,47.78 87.55,42.01 83.31,37.77 R112.2
R_EMAC[1]_TXCTL: length 43
  TOP w0.12: v1(103.35,59.64) 99.87,56.16 97.31,56.16 92.63,51.49 91.72,51.49 87.96,47.73 87.96,41.94 84.07,38.05 R111.2 ; v1(109.38,64.02) 109.29,64.02 109.28,64.04 U15.37
  INT_L3 w0.094: v1(109.38,64.02) 109.38,62.34 106.68,59.64 v1(103.35,59.64)
R_EMAC[1]_TXD0: length 40.7
  TOP w0.12: R113.2 82.55,36.93 82.96,37.34 82.96,37.9 87.2,42.14 87.2,47.9 91.76,52.47 91.91,52.47 92.1,52.29 92.24,52.29 92.35,52.4 92.35,52.54 92.17,52.73 92.17,52.87 92.27,52.98 92.42,52.98 92.6,52.8 92.75,52.8 92.86,52.9 92.86,53.05 92.68,53.23 92.68,53.38 92.78,53.49 92.93,53.49 93.11,53.31 93.26,53.31 93.37,53.41 93.37,53.56 93.19,53.74 93.19,53.89 93.29,54 93.44,54 93.62,53.82 93.77,53.82 93.88,53.92 93.88,54.07 93.69,54.25 93.69,54.4 93.8,54.51 93.95,54.51 94.13,54.32 94.28,54.32 94.38,54.43 94.38,54.58 94.2,54.76 94.2,54.91 94.39,55.09 94.97,55.09 96.98,57.1 99.11,57.1 101.96,59.94 101.96,60.93 103.75,62.73 U15.28
R_EMAC[1]_TXD1: length 44.2
  TOP w0.12: U15.27 103.25,62.74 101.57,61.06 101.57,60.1 101.4,59.92 101.25,59.92 101.01,60.17 100.86,60.17 100.75,60.06 100.75,59.91 101,59.67 101,59.52 100.89,59.41 100.74,59.41 100.5,59.66 100.35,59.66 100.24,59.55 100.24,59.4 100.49,59.16 100.49,59.01 100.38,58.9 100.23,58.9 99.99,59.15 99.84,59.15 99.73,59.04 99.73,58.89 99.98,58.65 99.98,58.5 99.87,58.4 99.73,58.4 99.48,58.64 99.33,58.64 99.23,58.54 99.23,58.39 99.47,58.14 99.47,57.99 98.93,57.45 98.06,57.45 97.96,57.56 97.96,57.78 97.85,57.89 97.7,57.89 97.6,57.78 97.6,57.56 97.49,57.45 97.34,57.45 97.24,57.56 97.24,57.78 97.13,57.89 96.98,57.89 96.88,57.78 96.88,57.56 96.77,57.45 96.09,57.45 95.86,57.23 95.86,56.96 96.05,56.77 96.05,56.62 95.94,56.52 95.79,56.52 95.61,56.7 95.46,56.7 95.36,56.6 95.36,56.45 95.54,56.27 95.54,56.12 95.43,56.01 95.28,56.01 95.1,56.19 94.95,56.19 94.85,56.09 94.85,55.94 95.03,55.76 95.03,55.61 94.92,55.5 94.77,55.5 94.59,55.68 94.44,55.68 86.79,48.03 86.79,42.24 82.6,38.05 82.6,37.67 81.79,36.86 R114.2
R_EMAC[1]_TXD2: length 43.4
  TOP w0.12: U15.26 102.75,62.65 101.73,61.62 101.17,61.62 100.89,61.34 100.89,60.68 100.76,60.55 100.48,60.55 100.36,60.67 100.36,61.37 100.15,61.57 99.75,61.57 99.47,61.29 99.47,60.92 99.57,60.81 99.84,60.81 99.95,60.71 99.95,60.56 99.84,60.45 99.57,60.45 99.47,60.35 99.47,60.2 99.57,60.09 99.84,60.09 99.95,59.99 99.95,59.84 99.84,59.73 99.57,59.73 99.47,59.63 99.47,59.39 98.74,58.66 98.74,58.49 98.86,58.37 98.86,58.12 98.7,57.96 98.35,57.96 98.04,58.27 95.99,58.27 95.39,57.67 95.39,57.21 86.44,48.26 86.44,42.37 82.19,38.13 81.41,38.13 81.18,37.9 81.18,37.62 81.07,37.52 80.79,37.52 80.67,37.4 80.67,37.19 80.78,37.09 81.07,37.09 81.18,36.98 81.18,36.57 R115.2
R_EMAC[1]_TXD3: length 45.3
  TOP w0.12: R118.2 80.26,38.38 81.18,39.29 82.83,39.29 86,42.47 86,43.18 85.9,43.29 85.4,43.29 85.29,43.39 85.29,43.54 85.4,43.65 85.9,43.65 86,43.75 86,43.9 85.9,44.01 85.4,44.01 85.29,44.11 85.29,44.26 85.4,44.37 85.9,44.37 86,44.47 86,44.62 85.9,44.73 85.4,44.73 85.29,44.83 85.29,44.98 85.4,45.09 85.9,45.09 86,45.19 86,48.34 94.95,57.28 94.95,57.91 95.76,58.72 98.22,58.72 98.91,59.41 98.91,61.54 99.47,62.1 99.95,62.1 100.06,62.21 100.06,62.66 100.16,62.76 100.31,62.76 100.42,62.66 100.42,62.21 100.52,62.1 100.67,62.1 100.78,62.21 100.78,62.66 100.88,62.76 101.03,62.76 101.14,62.66 101.14,62.21 101.24,62.1 101.6,62.1 102.25,62.76 U15.25
RDRXN: length 1.3
  TOP w0.102: C456.2 79.38,81.89 79.38,82.41 79.24,82.56 U33.4
RDRXP: length 1.3
  TOP w0.102: U33.5 79.74,82.15 C455.2
RDTXN: length 1.3
  TOP w0.102: C457.2 78.1,81.89 78.1,82.41 78.24,82.56 U33.2
RDTXP: length 1.3
  TOP w0.102: C454.1 77.74,82.15 U33.1
RESETIN: length 111.1
  TOP w0.12: S2.2 57.12,3.6 U12.3 56.29,7.94 55.88,8.35 53.25,8.35 v1(52.7,8.89) R52.2
  SIG_L5 w0.094: v1(52.7,8.89) 55.5,6.1 77.09,6.1 77.85,6.86 98.93,6.86 103,10.92 106.81,10.92 112.14,16.26 119.38,16.26 120.14,17.02 120.14,36.32 119.38,37.08 117.57,37.08 v1(116.71,37.94)
  BOTTOM w0.12: v1(116.71,37.94) 115.91,37.14 P18.34
RHDMI_TX0+: length 45
  TOP w0.102: FL3.4 v3(55.48,90.19)
  TOP w0.12: U11.AH17 v3(64.99,52.01)
  INT_L3 w0.094: v3(64.99,52.01) 64.99,53.5 59.42,59.07 59.42,78.25 57.93,79.74 56.86,79.74 55.68,80.91 55.68,88.2 55.6,88.28 55.43,88.28 55.35,88.36 55.35,88.48 55.43,88.56 55.6,88.56 55.68,88.65 55.68,88.76 55.6,88.84 55.43,88.84 55.35,88.93 55.35,89.04 55.43,89.13 55.6,89.13 55.68,89.21 55.68,89.98 v3(55.48,90.19)
RHDMI_TX0-: length 45
  TOP w0.102: FL3.1 v3(56.28,90.19)
  TOP w0.12: U11.AG17 v3(64.99,51.21)
  INT_L3 w0.094: v3(56.28,90.19) 56.08,89.99 56.08,81.08 57.02,80.14 58.09,80.14 59.82,78.41 59.82,59.24 65.38,53.67 65.38,51.6 v3(64.99,51.21)
RHDMI_TX1+: length 46
  TOP w0.102: FL2.4 v3(52.94,90.19)
  TOP w0.12: U11.AH18 v3(64.19,52.01)
  INT_L3 w0.094: v3(52.94,90.19) 53.14,89.98 53.14,89.28 53.06,89.2 52.89,89.2 52.81,89.12 52.81,89 52.89,88.92 53.06,88.92 53.14,88.83 53.14,88.72 53.06,88.64 52.89,88.64 52.81,88.55 52.81,88.44 52.89,88.35 53.06,88.35 53.14,88.27 53.14,83.2 54.21,82.13 54.21,79.01 54.48,78.74 54.48,76.76 54.26,76.54 54.26,68.78 54.9,68.14 54.9,64.99 54.39,64.48 54.39,62.32 59.07,57.64 59.65,57.64 64.19,53.11 v3(64.19,52.01)
RHDMI_TX1-: length 46
  TOP w0.102: FL2.1 v3(53.74,90.19)
  TOP w0.12: U11.AG18 v3(64.19,51.21)
  INT_L3 w0.094: v3(64.19,51.21) 64.59,51.6 64.59,53.27 59.82,58.04 59.24,58.04 54.79,62.49 54.79,64.31 55.06,64.59 55.3,64.82 55.3,67.98 55.3,68.31 54.66,68.94 54.66,76.38 54.88,76.6 54.88,78.91 54.61,79.18 54.61,82.3 53.54,83.36 53.54,89.99 v3(53.74,90.19)
RHDMI_TX2+: length 46.2
  TOP w0.12: U11.AH19 v3(63.39,52.01) ; FL1.4 v3(50.4,90.19)
  INT_L3 w0.094: v3(63.39,52.01) 63.39,52.56 59.87,56.08 59.18,56.08 52.18,63.08 52.18,80.86 50.6,82.44 50.6,88.43 50.52,88.52 50.35,88.52 50.27,88.6 50.27,88.71 50.35,88.8 50.52,88.8 50.6,88.88 50.6,89 50.52,89.08 50.35,89.08 50.27,89.16 50.27,89.28 50.35,89.36 50.52,89.36 50.6,89.44 50.6,89.98 v3(50.4,90.19)
RHDMI_TX2-: length 46.2
  TOP w0.12: U11.AG19 v3(63.39,51.21) ; FL1.1 v3(51.2,90.19)
  INT_L3 w0.094: v3(51.2,90.19) 51,89.99 51,82.6 52.58,81.03 52.58,63.25 59.34,56.48 60.03,56.48 63.78,52.73 63.78,52.01 63.79,52.01 63.79,51.6 v3(63.39,51.21)
RHDMI_TXC+: length 43.7
  TOP w0.102: FL4.4 v3(58.02,90.19)
  TOP w0.12: U11.AH16 v3(65.79,52.01)
  INT_L3 w0.094: v3(58.02,90.19) 58.22,89.98 58.22,89.19 58.14,89.11 57.97,89.11 57.89,89.03 57.89,88.91 57.97,88.83 58.14,88.83 58.22,88.74 58.22,88.63 58.14,88.54 57.97,88.54 57.89,88.46 57.89,88.35 57.97,88.26 58.14,88.26 58.22,88.18 58.22,81.8 60.56,79.46 60.56,60.22 65.81,54.97 65.81,52.03 v3(65.79,52.01)
RHDMI_TXC-: length 43.7
  TOP w0.102: FL4.1 v3(58.82,90.19)
  TOP w0.12: U11.AG16 v3(65.79,51.21)
  INT_L3 w0.094: v3(58.82,90.19) 58.62,89.99 58.62,81.97 60.96,79.63 60.96,60.38 66.21,55.13 66.21,51.63 v3(65.79,51.21)
RIGHT_IN: length 11.2
  BOTTOM w0.12: D11.2 42.04,7.18 P9.3 39.53,9.68 C256.2 R234.1
RIGHT_OUT: length 11.9
  BOTTOM w0.12: R228.1 26.45,12.79 C251.2 26.54,9.87 P8.3 29.24,7.18 D9.2
RSTOUTN: length 298.2
  TOP w0.12: U11.F23 v2(60.19,33.61) ; v2(93.83,44.57) 93.33,45.06 U22.K5 ; v1(59.94,14.48) 59.67,14.75 U18.31 ; U7.12 v1(25.91,51.05)
  INT_L3 w0.094: v1(25.91,51.05) 25.91,51.82 25.15,52.58 25.15,75.82 24,76.96 v1(24,82.93)
  SIG_L5 w0.094: v1(25.91,51.05) 19.81,44.95 19.81,43.94 17.4,41.53 17.4,34.29 19.56,32.13 26.8,32.13 27.3,32.64 31.62,32.64 33.91,30.35 33.91,24.64 33.53,24.26 33.53,18.8 34.67,17.65 48.13,17.65 51.31,20.83 51.31,25.65 54.23,28.57 56.01,28.57 57.4,29.97 57.4,30.61 57.65,30.85 57.93,30.85 58.14,31.06 58.14,31.34 58.35,31.56 59.44,31.56 59.74,31.86 59.74,33.16 v2(60.19,33.61) 60.19,33.87 60.56,34.25 60.56,34.54 60.82,34.8 71.51,34.8 71.81,35.09 71.81,35.36 72.08,35.63 72.34,35.63 72.61,35.89 72.61,36.16 72.88,36.43 73.14,36.43 73.41,36.69 73.41,36.96 73.68,37.23 73.94,37.23 74.21,37.49 74.21,37.76 74.43,37.98 74.74,37.98 75.01,38.25 75.01,38.56 75.23,38.78 75.54,38.78 75.81,39.05 75.81,39.36 76.03,39.58 76.34,39.58 76.61,39.85 76.61,40.16 76.83,40.39 77.31,40.39 77.6,40.67 78.1,40.67 78.25,40.82 78.92,40.82 79.27,41.17 81.64,41.17 81.92,40.89 86.61,40.89 89.53,43.81 93.07,43.81 v2(93.83,44.57)
  SIG_L10 w0.094: v2(93.83,44.57) 97.29,44.57 99.19,42.67 103.38,42.67 108.11,37.94 v1(115.82,37.94) ; v1(80.26,68) 80.26,70.61 77.24,73.64 75.97,73.64 75.06,74.55 75.06,77.5 74.38,78.17 72.43,78.17 71.44,77.18 66.46,77.18 v2(65.41,78.23) 65.07,78.56 65.07,79.76 66.24,80.92 66.24,85.57 65.23,86.59 49.53,86.59 43.33,80.39 33.4,80.39 32.13,81.66 29.21,81.66 27.18,83.69 24.77,83.69 v1(24,82.93)
  BOTTOM w0.12: U34.2 80.26,66.86 v1(80.26,68) ; P18.33 v1(115.82,37.94) ; 60.96,24.29 R40.1 61.09,23.78 61.09,21.08 60.33,20.32 60.33,16.26 61.21,15.37 61.21,13.46 60.96,13.21 60.2,13.21 59.94,13.46 v1(59.94,14.48) ; 60.96,24.29 R38.1 ; 60.96,24.29 60.96,25.65 60.16,26.45 59.27,26.45 58.99,26.73 58.99,28.11 58.56,28.54 R43.1 58.55,28.96 58.99,29.4 58.99,31.37 59.22,31.61 59.55,31.61 59.79,31.84 59.79,33.21 v2(60.19,33.61) ; v2(65.41,78.23) 65.91,78.23 66.17,77.98 R318.1
RTC_ISO: length 1.6
  TOP w0.12: U11.AF14 v2(68.19,50.41)
  BOTTOM w0.12: v2(68.19,50.41) 67.71,50.41 R57.2
RTC_X1: length 2.1
  TOP w0.12: U6.1 85.84,87.11 Y1.2 85.72,87.25 C32.1
RTC_X2: length 2.8
  TOP w0.12: U6.2 85.34,86.49 84.71,87.12 Y1.1 84.45,87.25 C31.1
RTCK: length 6.9
  BOTTOM w0.12: R63.2 69.94,27.59 70.27,27.27 70.27,26.13 70.48,25.91 70.48,24.3
RTCKR: length 6.6
  TOP w0.12: U11.E18 v2(64.19,32.81)
  SIG_L10 w0.094: v2(64.19,32.81) 64.61,32.38 65.9,32.38 66.17,32.12 66.17,30.35 66.55,29.97 v1(66.55,29.21)
  BOTTOM w0.12: R63.1 v1(66.55,29.21)
RXN_MUXC: length 2.9
  TOP w0.102: C456.1 79.25,80.43 79.5,80.18 79.5,79.76 79.17,79.42 79.17,78.24 U31.16
RXP_MUXC: length 2.9
  TOP w0.102: U31.15 79.52,78.24 79.52,79.27 79.86,79.61 79.86,80.15 80.14,80.43 C455.1
SAT_RXN: length 28.6
  TOP w0.102: U11.AH9 71.82,51.64 71.82,51.88 73.26,53.31 74.27,53.31 76.07,55.11 76.07,56.13 77.34,57.4 77.34,63.37 79.12,65.15 79.12,71.88 78.96,72.04 78.83,72.04 78.71,71.92 78.58,71.92 78.49,72.01 78.49,72.13 78.62,72.26 78.62,72.39 78.53,72.47 78.4,72.47 78.27,72.35 78.15,72.35 78.06,72.44 78.06,74.09 77.66,74.49 77.66,74.92 U31.6
SAT_RXP: length 28.6
  TOP w0.102: U31.7 78.02,74.91 78.02,74.63 78.41,74.23 78.41,73.09 79.48,72.03 79.48,65 77.7,63.23 77.7,57.25 76.43,55.98 76.43,54.97 74.42,52.96 73.41,52.96 72.18,51.73 72.18,51.2 U11.AG9
SAT_TXN: length 27.3
  TOP w0.102: 77.09,74.99 77.02,74.92 77.02,74.62 77.32,74.32 77.32,68.05 76.68,67.42 76.68,65.77 74.82,63.91 74.32,63.91 74.02,63.61 74.02,58.9 73.51,58.39 73.51,55.6 71.4,53.49 71.4,51.46 70.99,51.05 U11.AG10
SAT_TXP: length 27.2
  TOP w0.102: U31.4 76.67,74.92 76.67,74.47 76.96,74.17 76.96,68.2 76.33,67.56 76.33,65.91 74.68,64.26 74.17,64.26 73.66,63.75 73.66,59.05 73.15,58.54 73.15,55.75 71.04,53.64 71.04,53.41 70.97,53.34 70.81,53.34 70.74,53.27 70.74,53.18 70.81,53.11 70.97,53.11 71.04,53.04 71.04,52.95 70.97,52.88 70.81,52.88 70.74,52.82 70.74,52.72 70.81,52.65 70.97,52.65 71.04,52.59 71.04,51.66 U11.AH10
SATA_SEL: length 81.1
  TOP w0.12: v1(76.45,74.04) 76.09,74.4 U31.3
  SIG_L10 w0.094: v1(76.45,74.04) 76.45,78.61 74.84,80.23 74.84,85.61 73.36,87.1 47.75,87.1 42.68,82.03 40.28,82.03 39.64,82.68 29.21,82.68 28.19,83.69 28.07,83.69 27.56,84.2 v1(22.73,84.2)
  BOTTOM w0.12: P19.6 21.1,77.45 20.45,78.11 20.45,81.28 22.73,83.57 v1(22.73,84.2) ; R303.2 v1(76.45,74.04)
SCL_HUB: length 7.3
  TOP w0.12: U17.38 93.96,35.96 92.84,37.08 v1(89.66,37.08)
  BOTTOM w0.12: v1(89.66,37.08) 89.41,37.34 R393.2
SDA_HUB: length 7.2
  TOP w0.12: U17.37 94.46,36.22 94.36,36.32 v1(94.36,37.08)
  BOTTOM w0.12: v1(94.36,37.08) 94.11,37.34 90.84,37.34 R394.2
SERDES_CLKN: length 47
  TOP w0.102: C426.2 29.59,55.85 29.59,56.03 29.49,56.13 29.21,56.13 29.15,56.2 29.15,56.34 29.24,56.43 29.5,56.43 29.59,56.52 29.59,56.65 29.5,56.74 29.24,56.74 29.15,56.82 29.15,57.59 v1(29.34,57.78)
  TOP w0.12: U11.AH15 v2(66.59,52.01)
  SIG_L10 w0.094: v1(29.34,57.78) 29.34,57.78 29.94,57.78 33.01,60.85 49.82,60.85 51.74,58.93 59.31,58.93 64.64,53.59 65.46,53.59 66.59,52.47 v2(66.59,52.01)
  BOTTOM w0.12: v2(66.59,52.01) 66.68,51.91 R308.1
SERDES_CLKP: length 47.2
  TOP w0.102: C427.2 28.58,56.09 28.79,56.31 28.79,57.7 v1(28.7,57.78)
  TOP w0.12: U11.AG15 v2(66.59,51.21)
  SIG_L10 w0.094: v2(66.59,51.21) 66.19,51.6 66.19,52.3 65.3,53.2 64.48,53.2 59.14,58.53 51.58,58.53 49.66,60.45 33.27,60.45 30.12,57.3 29.18,57.3 v1(28.7,57.78)
  BOTTOM w0.12: R308.2 66.83,50.96 v2(66.59,51.21)
SERDES_IN_REFN: length 1.7
  TOP w0.12: C426.1 28.96,54.27 U7.5
SERDES_IN_REFP: length 1.5
  TOP w0.12: C427.1 28.46,54.65 U7.6
SMPS6: length 7.7
  TOP w1.016: R36.1 P2.3
  SIG_L5 w0.381: P2.3 47.71,75.48 ; P2.3 46.27,75.48 ; P2.3 47.71,76.92 ; P2.3 46.27,76.92
  vias: v1(60.2,85.47) v1(60.2,84.84) v1(60.2,84.2)
SMPS_1_2: length 7.7
  TOP w1.016: R34.1 P2.5
  SIG_L8 w0.381: P2.5 47.71,71.84 ; P2.5 46.27,71.84 ; P2.5 47.71,70.4 ; P2.5 46.27,70.4
  vias: v1(68.33,61.21) v1(68.33,60.58) v1(68.33,59.94) v1(69.85,61.21) v1(69.85,60.58) v1(69.85,59.94)
SMPS_4/5: length 7.7
  TOP w1.016: P2.2 R35.1
  SIG_L8 w0.381: P2.2 47.71,78.02 ; P2.2 46.27,78.02 ; P2.2 47.71,79.46 ; P2.2 46.27,79.46
  vias: v1(64.13,85.47) v1(64.82,85.47) v1(65.58,85.47) v1(67.61,85.45) v1(68.33,85.45) v1(69.06,85.42)
SS_SUSPEND: length 1.1
  TOP w0.12: R243.2 90.46,35.3 U17.45
SW1: length 1.6
  BOTTOM w0.381: v2(68.59,67.21) v2(68.59,68.01) v2(68.59,68.81)
  vias: v1(69.85,63.88) v1(69.85,63.25) v1(69.85,62.61)
SW2: length 1.6
  BOTTOM w0.381: v2(67.79,68.81) v2(67.79,68.01) v2(67.79,67.21)
  vias: v1(68.33,63.88) v1(68.33,63.25) v1(68.33,62.61)
SW3: length 1.6
  BOTTOM w0.381: v2(64.59,67.21) v2(64.59,68.01) v2(64.59,68.81)
  vias: v1(63.5,63.88) v1(63.5,63.25) v1(63.5,62.61)
SW4: length 1.6
  BOTTOM w0.381: v2(66.99,76.01) v2(66.99,76.81) v2(66.99,77.61)
  vias: v1(67.51,81.47) v1(68.3,81.48) v1(69.01,81.48)
SW5: length 1.6
  BOTTOM w0.381: v2(65.39,77.61) v2(65.39,76.81) v2(65.39,76.01)
  vias: v1(64.31,81.48) v1(65.02,81.51) v1(65.76,81.51)
SW6: length 0.8
  BOTTOM w0.381: v2(62.19,74.41) v2(61.39,74.41)
  vias: v1(60.63,81.53) v1(61.39,81.53) v1(62.13,81.53)
SW7:
  vias: v1(70.74,81.43) v1(71.4,81.43) v1(72.11,81.45) v2(69.37,77.62) v2(69.37,76.81) v2(69.37,76.02)
SW8:
  vias: v1(58.67,63.88) v1(58.67,63.25) v1(58.67,62.61) v2(61.39,69.61) v2(62.19,69.61)
TCK: length 16
  TOP w0.12: R64.1 v1(71.63,26.16) ; U11.E20 v2(62.59,32.81)
  SIG_L10 w0.094: v1(71.63,26.16) 71.63,26.29 71.23,26.69 71.23,27.45 70.23,28.45 68.33,28.45 66.93,29.84 66.93,31.05 66.94,31.06 66.94,32.96 66.68,33.23 63.25,33.23 62.82,32.81 v2(62.59,32.81)
TCLK: length 3.9
  TOP w0.12: R64.2 v1(71.63,22.35)
  BOTTOM w0.12: v1(71.63,22.35) 71.63,24.17 P4.11
TDI: length 11.9
  TOP w0.12: U11.D23 v2(60.19,32.01)
  SIG_L8 w0.094: v2(60.19,32.01) 60.19,31.76 61.41,30.54 61.41,29.9 62.87,28.45 64.39,28.45 v1(66.68,26.16)
  BOTTOM w0.12: P4.3 v1(66.68,26.16)
TDO: length 6.1
  BOTTOM w0.12: R61.2 65.66,27.18 66.04,26.8 66.93,26.8 67.56,26.16 68.96,26.16 69.22,25.91 P4.7
